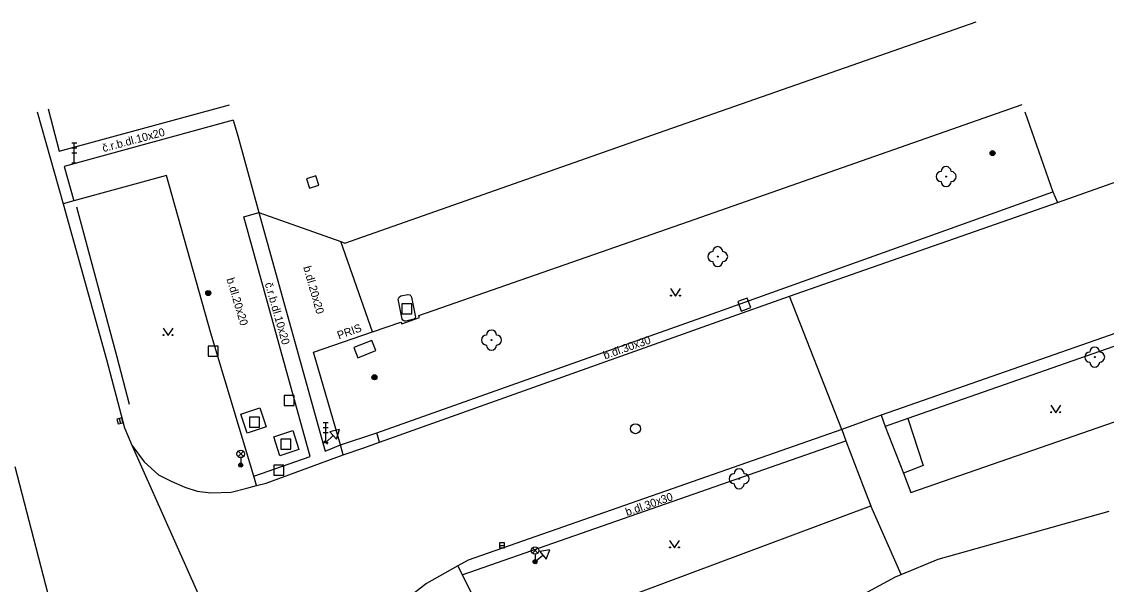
# Model space of a CAD drawing. Extents: x -599770 to -598493, y -1162076 to -1159209.
# Drawn here: x -598893.6 to -598839.3, y -1159360.6 to -1159332.5 of the extents above; entities that cross this region are included whole.
import ezdxf

# ---------------------------------------------------------------- set-up
doc = ezdxf.new("R2010")
doc.units = 0
doc.layers.add('Podklad', color=7, linetype='Continuous')

msp = doc.modelspace()

# ---------------------------------------------------------------- linework, layer by layer
at = {"layer": 'Podklad'}
for p, q in [((-598891.055, -1159338.54), (-598890.805, -1159338.54)), ((-598890.93, -1159339.54), (-598890.93, -1159338.54)), ((-598891.055, -1159338.79), (-598890.805, -1159338.79)), ((-598891.055, -1159339.04), (-598890.805, -1159339.04)), ((-598891.055, -1159339.54), (-598890.805, -1159339.54)), ((-598888.679, -1159352.308), (-598888.621, -1159352.552)), ((-598878.485, -1159352.51), (-598878.235, -1159352.51)), ((-598878.485, -1159352.76), (-598878.235, -1159352.76)), ((-598878.36, -1159353.51), (-598878.36, -1159352.51)), ((-598878.485, -1159353.01), (-598878.235, -1159353.01)), ((-598877.988, -1159353.162), (-598878.36, -1159353.51)), ((-598878.485, -1159353.51), (-598878.235, -1159353.51)), ((-598878.445, -1159353.419), (-598878.275, -1159353.601)), ((-598882.742, -1159354.21), (-598882.477, -1159353.945)), ((-598882.742, -1159353.945), (-598882.477, -1159354.21)), ((-598882.61, -1159354.265), (-598882.61, -1159354.64)), ((-598869.675, -1159358.65), (-598869.425, -1159358.65)), ((-598868.023, -1159359.04), (-598867.758, -1159358.775)), ((-598868.023, -1159358.775), (-598867.758, -1159359.04)), ((-598867.89, -1159359.095), (-598867.89, -1159359.47)), ((-598867.495, -1159359.149), (-598867.89, -1159359.47)), ((-598867.969, -1159359.373), (-598867.811, -1159359.567))]:
    msp.add_line(p, q, dxfattribs=at)
for points in [[(-598877.4, -1159343.54), (-598861.72, -1159338.03), (-598845.83, -1159332.48)], [(-598892.79, -1159336.98), (-598891.48, -1159341.58)], [(-598892.24, -1159336.83), (-598891.68, -1159338.95), (-598883.17, -1159336.63)], [(-598877.62, -1159353.63), (-598878.97, -1159349), (-598876.02, -1159347.98), (-598874.61, -1159347.5), (-598874.56, -1159347.58), (-598873.67, -1159347.26), (-598873.7, -1159347.16), (-598860.22, -1159342.46), (-598843.54, -1159336.62)], [(-598843.4, -1159336.98), (-598842, -1159340.99)], [(-598882.98, -1159337.4), (-598891.44, -1159339.71), (-598890.96, -1159341.44)], [(-598882.98, -1159337.4), (-598882.76, -1159338.19), (-598881.7, -1159342.02)], [(-598841.77, -1159341.51), (-598835.51, -1159339.3)], [(-598884.11, -1159348.05), (-598886.32, -1159340.16), (-598890.96, -1159341.44)], [(-598818.28, -1159340.8), (-598832.53, -1159345.83), (-598835.04, -1159346.71), (-598850.58, -1159352.14), (-598852.56, -1159352.86), (-598871.24, -1159359.39)], [(-598875.67, -1159353.49), (-598875.81, -1159353.02), (-598858.52, -1159346.89), (-598842, -1159340.99)], [(-598842, -1159340.99), (-598841.77, -1159341.51)], [(-598890.96, -1159341.44), (-598891.48, -1159341.58)], [(-598891.48, -1159341.58), (-598889.32, -1159349.36)], [(-598890.82, -1159341.74), (-598888.81, -1159349.23)], [(-598875.67, -1159353.49), (-598858.55, -1159347.39), (-598855.17, -1159346.2), (-598841.77, -1159341.51)], [(-598881.82, -1159355.66), (-598881.95, -1159355.2), (-598879.14, -1159354.21), (-598882.46, -1159342.23)], [(-598882.459, -1159342.233), (-598881.697, -1159342.02)], [(-598881.7, -1159342.02), (-598877.6, -1159343.47), (-598877.4, -1159343.54)], [(-598881.7, -1159342.02), (-598878.38, -1159353.94), (-598877.62, -1159353.63)], [(-598876.02, -1159347.98), (-598877.6, -1159343.47)], [(-598874.53, -1159347.35), (-598874.74, -1159346.35), (-598874.69, -1159346.25), (-598874.61, -1159346.18), (-598874.26, -1159346.11), (-598874.16, -1159346.13), (-598874.11, -1159346.18), (-598874.07, -1159346.25), (-598873.88, -1159347.17), (-598873.87, -1159347.23), (-598873.89, -1159347.29), (-598873.92, -1159347.32), (-598873.96, -1159347.34), (-598874.36, -1159347.45), (-598874.41, -1159347.45), (-598874.46, -1159347.43), (-598874.5, -1159347.4), (-598874.53, -1159347.35)], [(-598861.12, -1159345.815), (-598860.87, -1159346.19), (-598860.62, -1159345.815)], [(-598852.56, -1159352.86), (-598855.17, -1159346.2)], [(-598834.85, -1159347.28), (-598849.25, -1159352.31)], [(-598849.1, -1159356.01), (-598833.63, -1159350.64), (-598834.85, -1159347.28)], [(-598886.49, -1159347.795), (-598886.24, -1159348.17), (-598885.99, -1159347.795)], [(-598881.95, -1159355.2), (-598884.11, -1159348.05)], [(-598876.06, -1159348.41), (-598876.96, -1159348.77)], [(-598875.86, -1159348.92), (-598876.06, -1159348.41)], [(-598876.96, -1159348.77), (-598876.75, -1159349.28)], [(-598876.75, -1159349.28), (-598875.86, -1159348.92)], [(-598889.32, -1159349.36), (-598888.42, -1159352.77)], [(-598888.81, -1159349.23), (-598888.18, -1159351.6)], [(-598842.11, -1159351.645), (-598841.86, -1159352.02), (-598841.61, -1159351.645)], [(-598882.61, -1159352.1), (-598881.66, -1159351.78)], [(-598882.29, -1159353.05), (-598882.61, -1159352.1)], [(-598881.66, -1159351.78), (-598881.34, -1159352.73)], [(-598850.58, -1159352.14), (-598850.38, -1159352.71)], [(-598888.42, -1159352.77), (-598888.06, -1159353.65), (-598887.43, -1159354.48), (-598886.72, -1159355.12), (-598886.08, -1159355.45)], [(-598881.34, -1159352.73), (-598882.29, -1159353.05)], [(-598849.25, -1159352.31), (-598850.38, -1159352.71)], [(-598850.38, -1159352.71), (-598849.47, -1159355.05)], [(-598849.25, -1159352.31), (-598848.48, -1159354.66), (-598849.47, -1159355.05)], [(-598880.96, -1159353.22), (-598880.01, -1159352.91)], [(-598880.65, -1159354.17), (-598880.96, -1159353.22)], [(-598880.01, -1159352.91), (-598879.7, -1159353.86)], [(-598877.62, -1159353.63), (-598875.81, -1159353.02)], [(-598852.56, -1159352.86), (-598852.36, -1159353.43)], [(-598888.06, -1159353.65), (-598878.29, -1159375.54)], [(-598879.7, -1159353.86), (-598880.65, -1159354.17)], [(-598877.48, -1159354.12), (-598877.62, -1159353.63)], [(-598877.48, -1159354.12), (-598876.46, -1159353.78), (-598875.67, -1159353.49)], [(-598871.54, -1159360.12), (-598853.3, -1159353.76)], [(-598853.3, -1159353.76), (-598852.36, -1159353.43)], [(-598852.36, -1159353.43), (-598851.48, -1159355.7)], [(-598881.34, -1159355.54), (-598877.48, -1159354.12)], [(-598893.907, -1159354.703), (-598891.666, -1159363.322), (-598887.22, -1159380.27)], [(-598886.08, -1159355.45), (-598885.41, -1159355.74), (-598884.79, -1159355.94), (-598884.1, -1159356.03), (-598883.08, -1159355.99), (-598882.31, -1159355.79)], [(-598849.47, -1159355.05), (-598849.1, -1159356.01)], [(-598882.31, -1159355.79), (-598881.82, -1159355.66), (-598881.34, -1159355.54)], [(-598851.48, -1159355.7), (-598851.11, -1159356.68)], [(-598871.54, -1159360.12), (-598870.08, -1159363.01), (-598869.14, -1159363.41), (-598851.11, -1159356.68)], [(-598849.59, -1159360.11), (-598851.11, -1159356.68)], [(-598847.74, -1159359.34), (-598839.18, -1159356.94)], [(-598861.17, -1159358.405), (-598860.92, -1159358.78), (-598860.67, -1159358.405)], [(-598871.24, -1159359.39), (-598871.76, -1159359.67), (-598873.32, -1159360.55), (-598874.31, -1159361.32)], [(-598871.76, -1159359.67), (-598871.54, -1159360.12)], [(-598849.59, -1159360.11), (-598847.74, -1159359.34)], [(-598857.69, -1159364.45), (-598849.87, -1159360.22)], [(-598849.87, -1159360.22), (-598849.59, -1159360.11)]]:
    msp.add_lwpolyline(points, dxfattribs=at)
for points in [[(-598879.172, -1159340.804), (-598878.696, -1159340.652), (-598878.848, -1159340.176), (-598879.324, -1159340.328)], [(-598874.56, -1159347.08), (-598874.06, -1159347.08), (-598874.06, -1159346.58), (-598874.56, -1159346.58)], [(-598857.28, -1159346.3), (-598857.75, -1159346.47), (-598857.58, -1159346.94), (-598857.11, -1159346.77)], [(-598884.24, -1159349.2), (-598883.74, -1159349.2), (-598883.74, -1159348.7), (-598884.24, -1159348.7)], [(-598880.44, -1159351.66), (-598879.94, -1159351.66), (-598879.94, -1159351.16), (-598880.44, -1159351.16)], [(-598888.8, -1159352.337), (-598888.743, -1159352.58), (-598888.5, -1159352.523), (-598888.557, -1159352.28)], [(-598882.17, -1159352.75), (-598881.67, -1159352.75), (-598881.67, -1159352.25), (-598882.17, -1159352.25)], [(-598878.159, -1159352.98), (-598877.818, -1159353.345), (-598877.672, -1159352.866)], [(-598880.6, -1159353.85), (-598880.1, -1159353.85), (-598880.1, -1159353.35), (-598880.6, -1159353.35)], [(-598880.95, -1159355.15), (-598880.45, -1159355.15), (-598880.45, -1159354.65), (-598880.95, -1159354.65)], [(-598869.675, -1159358.775), (-598869.425, -1159358.775), (-598869.425, -1159358.525), (-598869.675, -1159358.525)], [(-598867.652, -1159358.955), (-598867.337, -1159359.343), (-598867.159, -1159358.876)]]:
    msp.add_lwpolyline(points, close=True, dxfattribs=at)
for centre, radius in [((-598845.02, -1159339.05), 0.125), ((-598845.02, -1159339.05), 0.1), ((-598845.02, -1159339.05), 0.075), ((-598845.02, -1159339.05), 0.05), ((-598845.02, -1159339.05), 0.025), ((-598847.34, -1159340.22), 0.025), ((-598858.76, -1159344.22), 0.025), ((-598884.23, -1159346.04), 0.125), ((-598884.23, -1159346.04), 0.1), ((-598884.23, -1159346.04), 0.075), ((-598884.23, -1159346.04), 0.05), ((-598884.23, -1159346.04), 0.025), ((-598861.095, -1159346.165), 0.025), ((-598860.645, -1159346.165), 0.025), ((-598886.465, -1159348.145), 0.025), ((-598886.015, -1159348.145), 0.025), ((-598870.07, -1159348.39), 0.025), ((-598839.91, -1159349.24), 0.025), ((-598875.92, -1159350.25), 0.125), ((-598875.92, -1159350.25), 0.1), ((-598875.92, -1159350.25), 0.075), ((-598875.92, -1159350.25), 0.05), ((-598875.92, -1159350.25), 0.025), ((-598842.085, -1159351.995), 0.025), ((-598841.635, -1159351.995), 0.025), ((-598862.87, -1159352.82), 0.25), ((-598882.61, -1159354.078), 0.188), ((-598882.61, -1159354.64), 0.1), ((-598882.61, -1159354.64), 0.0723), ((-598882.61, -1159354.64), 0.0438), ((-598857.69, -1159355.32), 0.025), ((-598867.89, -1159358.907), 0.188), ((-598861.145, -1159358.755), 0.025), ((-598860.695, -1159358.755), 0.025), ((-598867.89, -1159359.47), 0.1), ((-598867.89, -1159359.47), 0.0723), ((-598867.89, -1159359.47), 0.0438)]:
    msp.add_circle(centre, radius, dxfattribs=at)
for centre, start, end in [((-598847.34, -1159339.97), 0, 180), ((-598847.59, -1159340.22), 90, 270), ((-598847.09, -1159340.22), 270, 90), ((-598847.34, -1159340.47), 180, 0), ((-598859.01, -1159344.22), 90, 270), ((-598858.76, -1159343.97), 0, 180), ((-598858.51, -1159344.22), 270, 90), ((-598858.76, -1159344.47), 180, 0), ((-598870.07, -1159348.14), 0, 180), ((-598870.32, -1159348.39), 90, 270), ((-598869.82, -1159348.39), 270, 90), ((-598870.07, -1159348.64), 180, 0), ((-598839.91, -1159348.99), 0, 180), ((-598840.16, -1159349.24), 90, 270), ((-598839.91, -1159349.49), 180, 0), ((-598839.66, -1159349.24), 270, 90), ((-598857.69, -1159355.07), 0, 180), ((-598857.94, -1159355.32), 90, 270), ((-598857.44, -1159355.32), 270, 90), ((-598857.69, -1159355.57), 180, 0)]:
    msp.add_arc(centre, 0.25, start, end, dxfattribs=at)

# ---------------------------------------------------------------- texts
for s, rotation, p in [('č.r.b.dl.10x20', 15, (-598889.47, -1159339)), ('b.dl.20x20', 286, (-598879.49, -1159344.75)), ('b.dl.20x20', 286.6592, (-598883.32, -1159345.34)), ('č.r.b.dl.10x20', 286.02, (-598881.41, -1159345.57)), ('PRIS', 19.6582, (-598877.7, -1159348.36)), ('b.dl.30x30', 19.2774, (-598864.4, -1159349.36)), ('b.dl.30x30', 19.2774, (-598863.29, -1159357.19))]:
    msp.add_text(s, height=0.4, rotation=rotation, dxfattribs=at).set_placement(p)

doc.saveas('drawing.dxf')
